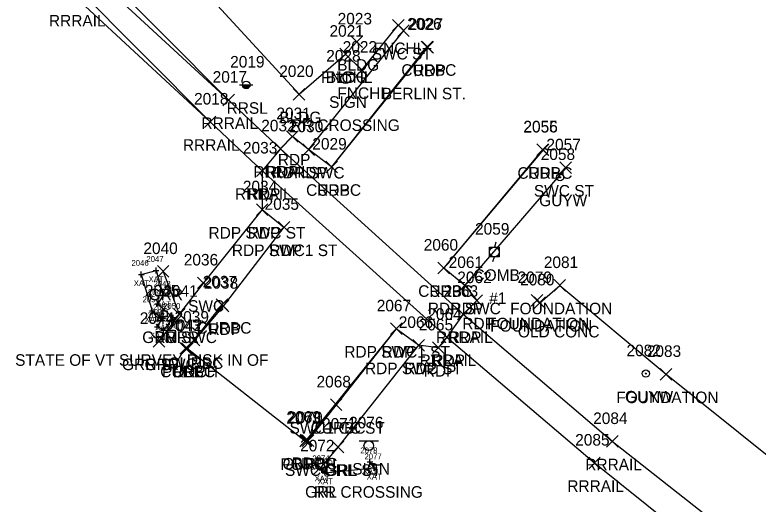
# Model space of a CAD drawing. Extents: x 1635588 to 1637550, y 621583 to 623638.
# Drawn here: x 1637037.4 to 1637166, y 621810.1 to 621894.7 of the extents above; entities that cross this region are included whole.
import ezdxf

# ---------------------------------------------------------------- set-up
doc = ezdxf.new("R2010")
doc.units = 0
for name, color, linetype in [('B_A', 7, 'Continuous'), ('B_I', 7, 'Continuous'), ('B_TIC', 7, 'Continuous'), ('BSUBM', 7, 'Continuous'), ('C_A', 7, 'Continuous'), ('C_C', 7, 'Continuous'), ('C_I', 7, 'Continuous'), ('CPBM', 7, 'Continuous'), ('L_A', 7, 'Continuous'), ('L_C', 7, 'Continuous'), ('L_I', 7, 'Continuous'), ('L_TIC', 7, 'Continuous'), ('LBC', 7, 'Continuous'), ('LBF', 7, 'Continuous'), ('LFNC', 7, 'Continuous'), ('P_A', 7, 'Continuous'), ('P_C', 7, 'Continuous'), ('P_I', 7, 'Continuous'), ('P_TIC', 7, 'Continuous'), ('PET', 7, 'Continuous'), ('R_A', 7, 'Continuous'), ('R_I', 7, 'Continuous'), ('R_TIC', 7, 'Continuous'), ('RC', 7, 'Continuous'), ('RGR', 7, 'Continuous'), ('RR', 7, 'Continuous'), ('RR_T', 7, 'Continuous'), ('RSW', 7, 'Continuous'), ('S_A', 7, 'Continuous'), ('S_C', 7, 'Continuous'), ('S_I', 7, 'Continuous'), ('SSGN', 7, 'Continuous'), ('U_A', 7, 'Continuous'), ('U_C', 7, 'Continuous'), ('U_I', 7, 'Continuous'), ('UP', 7, 'Continuous'), ('UPGW', 7, 'Continuous')]:
    doc.layers.add(name, color=color, linetype=linetype)

msp = doc.modelspace()

# ---------------------------------------------------------------- linework, layer by layer
at = {"layer": 'B_TIC'}
for p, q in [((1637059.28, 621849.83), (1637059.36, 621849.83)), ((1637059.28, 621849.83), (1637059.36, 621849.83)), ((1637061.83, 621850.52), (1637061.91, 621850.52)), ((1637063.07, 621846.22), (1637063.14, 621846.22)), ((1637062.11, 621844.77), (1637062.18, 621844.77)), ((1637061.17, 621843.54), (1637061.25, 621843.54)), ((1637061.17, 621843.54), (1637061.25, 621843.54)), ((1637062.98, 621842.2), (1637063.05, 621842.2)), ((1637064.77, 621842.38), (1637064.85, 621842.38)), ((1637062.05, 621840.8), (1637062.12, 621840.8)), ((1637063.12, 621840.2), (1637063.2, 621840.2)), ((1637098.86, 621817.41), (1637098.93, 621817.41)), ((1637099.59, 621816.37), (1637099.66, 621816.37)), ((1637090.56, 621816.04), (1637090.63, 621816.04)), ((1637091.11, 621815.55), (1637091.19, 621815.55))]:
    msp.add_line(p, q, dxfattribs=at)
for points in [[(1637058.78, 621849.83), (1637059.78, 621849.83)], [(1637058.78, 621849.83), (1637059.78, 621849.83)], [(1637059.28, 621849.33), (1637059.28, 621850.33)], [(1637059.28, 621849.33), (1637059.28, 621850.33)], [(1637061.33, 621850.52), (1637062.33, 621850.52)], [(1637061.83, 621850.02), (1637061.83, 621851.02)], [(1637062.56, 621846.22), (1637063.56, 621846.22)], [(1637063.06, 621845.72), (1637063.06, 621846.72)], [(1637061.6, 621844.77), (1637062.6, 621844.77)], [(1637062.1, 621844.27), (1637062.1, 621845.27)], [(1637060.67, 621843.54), (1637061.67, 621843.54)], [(1637060.67, 621843.54), (1637061.67, 621843.54)], [(1637061.17, 621843.04), (1637061.17, 621844.04)], [(1637061.17, 621843.04), (1637061.17, 621844.04)], [(1637062.47, 621842.2), (1637063.47, 621842.2)], [(1637062.97, 621841.7), (1637062.97, 621842.7)], [(1637064.27, 621842.38), (1637065.27, 621842.38)], [(1637064.77, 621841.88), (1637064.77, 621842.88)], [(1637061.54, 621840.8), (1637062.54, 621840.8)], [(1637062.04, 621840.3), (1637062.04, 621841.3)], [(1637062.62, 621840.2), (1637063.62, 621840.2)], [(1637063.12, 621839.7), (1637063.12, 621840.7)], [(1637098.86, 621816.91), (1637098.86, 621817.91)], [(1637090.55, 621815.54), (1637090.55, 621816.54)], [(1637098.36, 621817.41), (1637099.36, 621817.41)], [(1637099.08, 621816.37), (1637100.08, 621816.37)], [(1637099.58, 621815.87), (1637099.58, 621816.87)], [(1637090.05, 621816.04), (1637091.05, 621816.04)], [(1637090.61, 621815.55), (1637091.61, 621815.55)], [(1637091.11, 621815.05), (1637091.11, 621816.05)]]:
    msp.add_lwpolyline(points, dxfattribs=at)
at = {"layer": 'BSUBM'}
for points in [[(1637059.28, 621849.83), (1637061.83, 621850.52), (1637063.06, 621846.22), (1637062.1, 621844.77), (1637064.77, 621842.38), (1637063.12, 621840.2), (1637062.04, 621840.8), (1637062.97, 621842.2), (1637061.17, 621843.54)], [(1637059.28, 621849.83), (1637061.17, 621843.54)], [(1637090.55, 621816.04), (1637091.11, 621815.55), (1637099.58, 621816.37), (1637098.86, 621817.41)]]:
    msp.add_lwpolyline(points, dxfattribs=at)
at = {"layer": 'CPBM'}
for p, q in [((1637062.74, 621842.53), (1637062.74, 621843.53)), ((1637062.74, 621843.53), (1637063.74, 621843.53)), ((1637063.74, 621843.53), (1637063.74, 621842.53)), ((1637063.74, 621842.53), (1637062.74, 621842.53)), ((1637063.24, 621843.04), (1637063.24, 621843.04)), ((1637063.24, 621843.04), (1637063.24, 621843.04))]:
    msp.add_line(p, q, dxfattribs=at)
at = {"layer": 'L_TIC'}
for points in [[(1637102.75, 621891.96), (1637104.75, 621893.96)], [(1637104.75, 621891.96), (1637102.75, 621893.96)], [(1637095.59, 621889.08), (1637097.59, 621891.08)], [(1637097.59, 621889.08), (1637095.59, 621891.08)], [(1637093.62, 621886.96), (1637095.62, 621888.96)], [(1637095.62, 621886.96), (1637093.62, 621888.96)], [(1637093.62, 621886.96), (1637095.62, 621888.96)], [(1637095.62, 621886.96), (1637093.62, 621888.96)], [(1637096.47, 621884.2), (1637098.47, 621886.2)], [(1637098.47, 621884.2), (1637096.47, 621886.2)], [(1637085.58, 621880), (1637087.58, 621882)], [(1637087.58, 621880), (1637085.58, 621882)], [(1637130.72, 621846.95), (1637132.72, 621848.95)], [(1637132.72, 621846.95), (1637130.72, 621848.95)], [(1637126.75, 621844.35), (1637128.75, 621846.35)], [(1637128.75, 621844.35), (1637126.75, 621846.35)], [(1637127.26, 621843.95), (1637129.26, 621845.95)], [(1637129.26, 621843.95), (1637127.26, 621845.95)], [(1637066.26, 621836.04), (1637068.26, 621838.04)], [(1637068.26, 621836.04), (1637066.26, 621838.04)], [(1637149.11, 621831.58), (1637151.11, 621833.58)], [(1637151.11, 621831.58), (1637149.11, 621833.58)], [(1637086.72, 621820.02), (1637088.72, 621822.02)], [(1637088.72, 621820.02), (1637086.72, 621822.02)]]:
    msp.add_lwpolyline(points, dxfattribs=at)
at = {"layer": 'LBC'}
for points in [[(1636885.66, 622098.09), (1636886.49, 622098.53), (1637000.47, 621974.51), (1637086.58, 621881), (1637094.62, 621887.96), (1637096.59, 621890.08)], [(1637127.75, 621845.35), (1637128.26, 621844.95), (1637131.72, 621847.95), (1637150.11, 621832.58), (1637193.82, 621797.61), (1637199.24, 621804.01)]]:
    msp.add_lwpolyline(points, dxfattribs=at)
at = {"layer": 'LBF'}
msp.add_lwpolyline([(1637067.26, 621837.04), (1637087.72, 621821.02)], dxfattribs=at)
at = {"layer": 'LFNC'}
msp.add_lwpolyline([(1637094.62, 621887.96), (1637097.47, 621885.2), (1637103.75, 621892.96)], dxfattribs=at)
at = {"layer": 'P_TIC'}
for points in [[(1637107.88, 621888.13), (1637109.88, 621890.13)], [(1637109.88, 621888.13), (1637107.88, 621890.13)], [(1637084.43, 621872.7), (1637086.43, 621874.7)], [(1637086.43, 621872.7), (1637084.43, 621874.7)], [(1637082.38, 621870.59), (1637084.38, 621872.59)], [(1637084.38, 621870.59), (1637082.38, 621872.59)], [(1637087.24, 621870.44), (1637089.24, 621872.44)], [(1637089.24, 621870.44), (1637087.24, 621872.44)], [(1637127.74, 621870.42), (1637129.74, 621872.42)], [(1637129.74, 621870.42), (1637127.74, 621872.42)], [(1637091.22, 621867.44), (1637093.22, 621869.44)], [(1637093.22, 621867.44), (1637091.22, 621869.44)], [(1637079.21, 621866.76), (1637081.21, 621868.76)], [(1637081.21, 621866.76), (1637079.21, 621868.76)], [(1637079.2, 621860.05), (1637081.2, 621862.05)], [(1637081.2, 621860.05), (1637079.2, 621862.05)], [(1637082.96, 621857.02), (1637084.96, 621859.02)], [(1637084.96, 621857.02), (1637082.96, 621859.02)], [(1637110.63, 621849.97), (1637112.63, 621851.97)], [(1637112.63, 621849.97), (1637110.63, 621851.97)], [(1637114.3, 621846.96), (1637116.3, 621848.96)], [(1637116.3, 621846.96), (1637114.3, 621848.96)], [(1637116.35, 621844.34), (1637118.35, 621846.34)], [(1637118.35, 621844.34), (1637116.35, 621846.34)], [(1637072.43, 621843.38), (1637074.43, 621845.38)], [(1637074.43, 621843.38), (1637072.43, 621845.38)], [(1637114.01, 621841.98), (1637116.01, 621843.98)], [(1637116.01, 621841.98), (1637114.01, 621843.98)], [(1637102.41, 621839.46), (1637104.41, 621841.46)], [(1637104.41, 621839.46), (1637102.41, 621841.46)], [(1637111.17, 621838), (1637113.17, 621840)], [(1637113.17, 621838), (1637111.17, 621840)], [(1637106.28, 621836.59), (1637108.28, 621838.59)], [(1637108.28, 621836.59), (1637106.28, 621838.59)], [(1637109.69, 621836.17), (1637111.69, 621838.17)], [(1637111.69, 621836.17), (1637109.69, 621838.17)], [(1637066.26, 621836.04), (1637068.26, 621838.04)], [(1637068.26, 621836.04), (1637066.26, 621838.04)], [(1637086.82, 621820.19), (1637088.82, 621822.19)], [(1637088.82, 621820.19), (1637086.82, 621822.19)]]:
    msp.add_lwpolyline(points, dxfattribs=at)
at = {"layer": 'PET'}
for points in [[(1637108.88, 621889.13), (1637092.22, 621868.44), (1637088.24, 621871.44), (1637085.43, 621873.7), (1637083.38, 621871.59), (1637080.21, 621867.76), (1637080.2, 621861.05), (1637083.96, 621858.02), (1637073.43, 621844.38), (1637067.26, 621837.04)], [(1637128.74, 621871.42), (1637111.63, 621850.97), (1637115.3, 621847.96), (1637117.35, 621845.34), (1637115.01, 621842.98), (1637112.17, 621839), (1637110.69, 621837.17), (1637107.28, 621837.59), (1637103.41, 621840.46), (1637087.82, 621821.19)]]:
    msp.add_lwpolyline(points, dxfattribs=at)
at = {"layer": 'R_TIC'}
for points in [[(1637103.67, 621891.02), (1637105.67, 621893.02)], [(1637105.67, 621891.02), (1637103.67, 621893.02)], [(1637107.71, 621888.2), (1637109.71, 621890.2)], [(1637109.71, 621888.2), (1637107.71, 621890.2)], [(1637073.4, 621879.01), (1637075.4, 621881.01)], [(1637075.4, 621879.01), (1637073.4, 621881.01)], [(1637073.4, 621879.01), (1637075.4, 621881.01)], [(1637075.4, 621879.01), (1637073.4, 621881.01)], [(1637070.19, 621875.23), (1637072.19, 621877.23)], [(1637072.19, 621875.23), (1637070.19, 621877.23)], [(1637070.19, 621875.23), (1637072.19, 621877.23)], [(1637072.19, 621875.23), (1637070.19, 621877.23)], [(1637082.38, 621870.59), (1637084.38, 621872.59)], [(1637084.38, 621870.59), (1637082.38, 621872.59)], [(1637087.24, 621870.44), (1637089.24, 621872.44)], [(1637089.24, 621870.44), (1637087.24, 621872.44)], [(1637127.81, 621870.39), (1637129.81, 621872.39)], [(1637129.81, 621870.39), (1637127.81, 621872.39)], [(1637091.22, 621867.44), (1637093.22, 621869.44)], [(1637093.22, 621867.44), (1637091.22, 621869.44)], [(1637131.74, 621867.31), (1637133.74, 621869.31)], [(1637133.74, 621867.31), (1637131.74, 621869.31)], [(1637079.21, 621866.76), (1637081.21, 621868.76)], [(1637081.21, 621866.76), (1637079.21, 621868.76)], [(1637079.2, 621860.05), (1637081.2, 621862.05)], [(1637081.2, 621860.05), (1637079.2, 621862.05)], [(1637082.96, 621857.02), (1637084.96, 621859.02)], [(1637084.96, 621857.02), (1637082.96, 621859.02)], [(1637062.06, 621849.37), (1637064.06, 621851.37)], [(1637064.06, 621849.37), (1637062.06, 621851.37)], [(1637110.63, 621849.97), (1637112.63, 621851.97)], [(1637112.63, 621849.97), (1637110.63, 621851.97)], [(1637069.02, 621847.39), (1637071.02, 621849.39)], [(1637071.02, 621847.39), (1637069.02, 621849.39)], [(1637114.3, 621846.96), (1637116.3, 621848.96)], [(1637116.3, 621846.96), (1637114.3, 621848.96)], [(1637072.24, 621843.6), (1637074.24, 621845.6)], [(1637074.24, 621843.6), (1637072.24, 621845.6)], [(1637064.86, 621841.98), (1637066.86, 621843.98)], [(1637066.86, 621841.98), (1637064.86, 621843.98)], [(1637064.86, 621841.98), (1637066.86, 621843.98)], [(1637066.86, 621841.98), (1637064.86, 621843.98)], [(1637114.01, 621841.98), (1637116.01, 621843.98)], [(1637116.01, 621841.98), (1637114.01, 621843.98)], [(1637102.41, 621839.46), (1637104.41, 621841.46)], [(1637104.41, 621839.46), (1637102.41, 621841.46)], [(1637067.39, 621837.5), (1637069.39, 621839.5)], [(1637069.39, 621837.5), (1637067.39, 621839.5)], [(1637111.17, 621838), (1637113.17, 621840)], [(1637113.17, 621838), (1637111.17, 621840)], [(1637061.36, 621837.29), (1637063.36, 621839.29)], [(1637063.36, 621837.29), (1637061.36, 621839.29)], [(1637061.36, 621837.29), (1637063.36, 621839.29)], [(1637063.36, 621837.29), (1637061.36, 621839.29)], [(1637106.28, 621836.59), (1637108.28, 621838.59)], [(1637108.28, 621836.59), (1637106.28, 621838.59)], [(1637065.97, 621836.06), (1637067.97, 621838.06)], [(1637067.97, 621836.06), (1637065.97, 621838.06)], [(1637092, 621826.3), (1637094, 621828.3)], [(1637094, 621826.3), (1637092, 621828.3)], [(1637092, 621826.3), (1637094, 621828.3)], [(1637094, 621826.3), (1637092, 621828.3)], [(1637087.13, 621820.1), (1637089.13, 621822.1)], [(1637089.13, 621820.1), (1637087.13, 621822.1)], [(1637139.82, 621819.97), (1637141.82, 621821.97)], [(1637141.82, 621819.97), (1637139.82, 621821.97)], [(1637092.34, 621819), (1637094.34, 621821)], [(1637094.34, 621819), (1637092.34, 621821)], [(1637092.34, 621819), (1637094.34, 621821)], [(1637094.34, 621819), (1637092.34, 621821)], [(1637136.72, 621816.24), (1637138.72, 621818.24)], [(1637138.72, 621816.24), (1637136.72, 621818.24)], [(1637089.1, 621815.24), (1637091.1, 621817.24)], [(1637091.1, 621815.24), (1637089.1, 621817.24)]]:
    msp.add_lwpolyline(points, dxfattribs=at)
at = {"layer": 'RC'}
for points in [[(1637108.71, 621889.2), (1637092.22, 621868.44)], [(1637128.81, 621871.39), (1637111.63, 621850.97)], [(1637073.24, 621844.6), (1637068.39, 621838.5), (1637066.97, 621837.06)], [(1637093, 621827.3), (1637088.13, 621821.1)]]:
    msp.add_lwpolyline(points, dxfattribs=at)
at = {"layer": 'RGR'}
for points in [[(1637063.06, 621850.37), (1637065.86, 621842.98), (1637062.36, 621838.29)], [(1637093.34, 621820), (1637090.1, 621816.24)]]:
    msp.add_lwpolyline(points, dxfattribs=at)
at = {"layer": 'RR'}
for points in [[(1636647.57, 622303.46), (1636681.53, 622274.07), (1636698.35, 622258.6), (1636736.07, 622216.66), (1636772.81, 622171.31), (1636793.48, 622145.5), (1636799.12, 622138.4), (1636815.41, 622118.42), (1636845.94, 622085.12), (1636908.55, 622026.21), (1636983.07, 621959.74), (1637027.08, 621922.66), (1637050.39, 621902.14), (1637074.4, 621880.01)], [(1636645.23, 622298.69), (1636678.25, 622270.68), (1636695.49, 622253.83), (1636732.46, 622213.3), (1636769.51, 622167.71), (1636788.83, 622143.09), (1636795.06, 622135.55), (1636811.52, 622115.54), (1636841.96, 622081.95), (1636905.16, 622022.78), (1636979.87, 621956.02), (1637024.02, 621918.73), (1637048, 621897.73), (1637071.19, 621876.23)], [(1637026.25, 621930.62), (1637051.37, 621903.17), (1637074.4, 621880.01), (1637083.38, 621871.59), (1637115.01, 621842.98), (1637140.82, 621820.97), (1637163.57, 621803.06), (1637178.63, 621791.62), (1637197.58, 621777.98), (1637205.69, 621772.14), (1637224.52, 621759.19), (1637253.9, 621739.72), (1637289.58, 621717.58), (1637320.59, 621699.03)], [(1637027.08, 621922.66), (1637047.82, 621899.75), (1637071.19, 621876.23), (1637080.21, 621867.76), (1637112.17, 621839), (1637137.72, 621817.24), (1637160.21, 621799.22), (1637175.91, 621787.14), (1637194.67, 621774), (1637203.09, 621767.92), (1637221.71, 621755.12), (1637251.64, 621735.37), (1637287.01, 621713.34), (1637318.07, 621694.59)]]:
    msp.add_lwpolyline(points, dxfattribs=at)
at = {"layer": 'RR_T'}
for p, q in [((1637076.3, 621882.63), (1637078.59, 621882.63)), ((1637076.79, 621882.55), (1637078.09, 621882.55)), ((1637076.81, 621882.46), (1637078.08, 621882.46)), ((1637076.84, 621882.38), (1637078.05, 621882.38)), ((1637076.88, 621882.3), (1637078.01, 621882.3)), ((1637076.93, 621882.22), (1637077.96, 621882.22)), ((1637077.01, 621882.14), (1637077.88, 621882.14)), ((1637077.13, 621882.05), (1637077.76, 621882.05)), ((1637077.44, 621882.55), (1637077.44, 621882.71))]:
    msp.add_line(p, q, dxfattribs=at)
msp.add_circle((1637077.44, 621882.63), 0.656, dxfattribs=at)
at = {"layer": 'RSW'}
for points in [[(1637104.67, 621892.02), (1637088.24, 621871.44)], [(1637132.74, 621868.31), (1637115.3, 621847.96)], [(1637080.2, 621861.05), (1637070.02, 621848.39), (1637065.86, 621842.98), (1637062.36, 621838.29)], [(1637103.41, 621840.46), (1637093, 621827.3)], [(1637107.28, 621837.59), (1637093.34, 621820)]]:
    msp.add_lwpolyline(points, dxfattribs=at)
at = {"layer": 'SSGN'}
for p, q in [((1637093, 621884.51), (1637096.34, 621884.51)), ((1637094.65, 621883.68), (1637094.65, 621883.68)), ((1637097.01, 621821.08), (1637100.34, 621821.08)), ((1637098.65, 621820.24), (1637098.65, 621820.24))]:
    msp.add_line(p, q, dxfattribs=at)
for centre in [(1637094.65, 621883.68), (1637098.65, 621820.24)]:
    msp.add_circle(centre, 0.833, dxfattribs=at)
at = {"layer": 'UP'}
for p, q in [((1637120.64, 621855.4), (1637120.39, 621854.57)), ((1637119.55, 621852.9), (1637119.55, 621854.57)), ((1637119.55, 621854.57), (1637121.22, 621854.57)), ((1637120.39, 621853.73), (1637120.39, 621853.73)), ((1637121.22, 621854.57), (1637121.22, 621852.9)), ((1637121.22, 621852.9), (1637119.55, 621852.9)), ((1637120.14, 621852.07), (1637120.39, 621852.9))]:
    msp.add_line(p, q, dxfattribs=at)
msp.add_circle((1637120.39, 621853.73), 0.833, dxfattribs=at)
at = {"layer": 'UPGW'}
for centre, radius in [((1637131.75, 621866.64), 0.625), ((1637131.75, 621866.64), 0.0833), ((1637146.6, 621832.7), 0.625), ((1637146.6, 621832.7), 0.0833)]:
    msp.add_circle(centre, radius, dxfattribs=at)

# ---------------------------------------------------------------- texts
at = {"layer": 'B_A'}
for p in [(1637057.98, 621847.83), (1637057.98, 621847.83), (1637060.53, 621848.52), (1637061.77, 621844.22), (1637060.81, 621842.77), (1637059.87, 621841.54), (1637059.87, 621841.54), (1637061.68, 621840.2), (1637063.48, 621840.38), (1637060.75, 621838.8), (1637061.82, 621838.2), (1637097.56, 621815.41), (1637089.26, 621814.04), (1637098.29, 621814.37), (1637089.82, 621813.55)]:
    msp.add_text('XAT', height=1, dxfattribs=at).set_placement(p)
at = {"layer": 'B_I'}
for s, p in [('2046', (1637057.58, 621851.33)), ('2046', (1637057.58, 621851.33)), ('2047', (1637060.16, 621852.02)), ('2048', (1637061.39, 621847.72)), ('2049', (1637060.43, 621846.27)), ('2054', (1637059.5, 621845.04)), ('2054', (1637059.5, 621845.04)), ('2053', (1637061.3, 621843.7)), ('2050', (1637063.06, 621843.88)), ('2052', (1637060.37, 621842.3)), ('2051', (1637061.73, 621841.7)), ('2078', (1637097.19, 621818.91)), ('2077', (1637097.91, 621817.87)), ('2074', (1637088.89, 621817.54)), ('2075', (1637089.44, 621817.05))]:
    msp.add_text(s, height=1, dxfattribs=at).set_placement(p)
at = {"layer": 'C_A'}
msp.add_text('BM', height=2, dxfattribs=at).set_placement((1637061.56, 621838.04))
at = {"layer": 'C_C'}
msp.add_text('STATE OF VT SURVEY DISK IN OF', height=2, dxfattribs=at).set_placement((1637037.44, 621834.04))
at = {"layer": 'C_I'}
msp.add_text('2045', height=2, dxfattribs=at).set_placement((1637059.9, 621846.04))
at = {"layer": 'L_A'}
for s, p in [('FNCHL', (1637099.5, 621887.96)), ('BLDG', (1637093.18, 621885.08)), ('FNCHL', (1637090.37, 621882.96)), ('BLDG', (1637091.21, 621882.96)), ('FNCHL', (1637093.22, 621880.2)), ('BLDG', (1637083.17, 621876)), ('FOUNDATION', (1637123.12, 621842.95)), ('FOUNDATION', (1637119.14, 621840.35)), ('FOUNDATION', (1637119.66, 621839.95)), ('PORCH', (1637062.88, 621832.04)), ('FOUNDATION', (1637141.5, 621827.58)), ('PORCH', (1637083.34, 621816.02))]:
    msp.add_text(s, height=2, dxfattribs=at).set_placement(p)
at = {"layer": 'L_C'}
msp.add_text('OLD CONC', height=2, dxfattribs=at).set_placement((1637124.47, 621838.95))
at = {"layer": 'L_I'}
for s, p in [('2023', (1637093.26, 621893.08)), ('2021', (1637091.85, 621890.96)), ('2021', (1637091.85, 621890.96)), ('2022', (1637094.13, 621888.2)), ('2020', (1637083.15, 621884)), ('2081', (1637128.95, 621850.95)), ('2079', (1637124.4, 621848.35)), ('2080', (1637124.84, 621847.95)), ('2042', (1637063.92, 621840.04)), ('2083', (1637146.77, 621835.58)), ('2073', (1637084.38, 621824.02))]:
    msp.add_text(s, height=2, dxfattribs=at).set_placement(p)
at = {"layer": 'P_A'}
for p in [(1637106.37, 621884.13), (1637082.91, 621868.7), (1637080.87, 621866.59), (1637085.73, 621866.44), (1637126.23, 621866.42), (1637089.71, 621863.44), (1637077.7, 621862.76), (1637077.69, 621856.05), (1637081.45, 621853.02), (1637109.12, 621845.97), (1637112.79, 621842.96), (1637114.84, 621840.34), (1637070.92, 621839.38), (1637112.5, 621837.98), (1637100.9, 621835.46), (1637109.66, 621834), (1637104.77, 621832.59), (1637064.74, 621832.04), (1637108.17, 621832.17), (1637085.3, 621816.19)]:
    msp.add_text('RDP', height=2, dxfattribs=at).set_placement(p)
at = {"layer": 'P_C'}
msp.add_text('BERLIN ST.', height=2, dxfattribs=at).set_placement((1637100.9, 621880.13))
at = {"layer": 'P_I'}
for s, p in [('2027', (1637105.55, 621892.13)), ('2031', (1637082.66, 621876.7)), ('2032', (1637080.04, 621874.59)), ('2030', (1637084.82, 621874.44)), ('2055', (1637125.41, 621874.42)), ('2029', (1637088.88, 621871.44)), ('2033', (1637076.87, 621870.76)), ('2034', (1637076.86, 621864.05)), ('2035', (1637080.62, 621861.02)), ('2060', (1637108.16, 621853.97)), ('2061', (1637112.48, 621850.96)), ('2062', (1637113.97, 621848.34)), ('2038', (1637070.09, 621847.38)), ('2063', (1637111.62, 621845.98)), ('2067', (1637100.03, 621843.46)), ('2064', (1637108.78, 621842)), ('2042', (1637063.92, 621840.04)), ('2066', (1637103.84, 621840.59)), ('2065', (1637107.3, 621840.17)), ('2069', (1637084.42, 621824.19))]:
    msp.add_text(s, height=2, dxfattribs=at).set_placement(p)
at = {"layer": 'R_A'}
for s, p in [('RRRAIL', (1637043.29, 621892.73)), ('SWC ST', (1637099.16, 621887.02)), ('CURBC', (1637104.29, 621884.2)), ('RRSL', (1637074.04, 621877.63)), ('RRRAIL', (1637069.69, 621875.01)), ('RRRAIL', (1637069.69, 621875.01)), ('RRRAIL', (1637066.48, 621871.23)), ('RRRAIL', (1637066.48, 621871.23)), ('RRRAIL', (1637078.67, 621866.59)), ('RDP SWC', (1637081.83, 621866.44)), ('CURBC', (1637124.39, 621866.39)), ('CURBC', (1637087.81, 621863.44)), ('SWC ST', (1637127.23, 621863.31)), ('RRRAIL', (1637075.5, 621862.76)), ('RDP SWC ST', (1637070.91, 621856.05)), ('RDP SWC1 ST', (1637074.96, 621853.02)), ('GRR', (1637060.55, 621845.37)), ('CURBC', (1637107.21, 621845.97)), ('SWC', (1637067.38, 621843.39)), ('RDP SWC', (1637108.88, 621842.96)), ('CURBC', (1637068.83, 621839.6)), ('GRR SWC', (1637059.44, 621837.98)), ('GRR', (1637063.35, 621837.98)), ('RRRAIL', (1637110.3, 621837.98)), ('RDP SWC1 ST', (1637094.41, 621835.46)), ('RRRAIL', (1637107.46, 621834)), ('GRR SWC', (1637055.94, 621833.29)), ('GRR', (1637059.85, 621833.29)), ('CURBC', (1637063.97, 621833.5)), ('RDP SWC ST', (1637097.99, 621832.59)), ('CURBC', (1637062.55, 621832.06)), ('SWC1 CC ST', (1637084.94, 621822.3)), ('CURBC', (1637088.58, 621822.3)), ('CURBC', (1637083.72, 621816.1)), ('RRRAIL', (1637136.12, 621815.97)), ('SWC GRL ST', (1637084.15, 621815)), ('GRL', (1637090.88, 621815)), ('RRRAIL', (1637133.01, 621812.24)), ('GRL', (1637087.64, 621811.24))]:
    msp.add_text(s, height=2, dxfattribs=at).set_placement(p)
at = {"layer": 'R_I'}
for s, p in [('2026', (1637105.31, 621892.2)), ('2019', (1637074.66, 621885.63)), ('2017', (1637071.63, 621883.01)), ('2017', (1637071.63, 621883.01)), ('2018', (1637068.41, 621879.23)), ('2018', (1637068.41, 621879.23)), ('2032', (1637080.04, 621874.59)), ('2030', (1637084.82, 621874.44)), ('2056', (1637125.42, 621874.39)), ('2029', (1637088.88, 621871.44)), ('2057', (1637129.4, 621871.31)), ('2033', (1637076.87, 621870.76)), ('2034', (1637076.86, 621864.05)), ('2035', (1637080.62, 621861.02)), ('2040', (1637059.64, 621853.37)), ('2060', (1637108.16, 621853.97)), ('2036', (1637066.63, 621851.39)), ('2061', (1637112.48, 621850.96)), ('2037', (1637069.91, 621847.6)), ('2041', (1637063.09, 621845.98)), ('2041', (1637063.09, 621845.98)), ('2063', (1637111.62, 621845.98)), ('2067', (1637100.03, 621843.46)), ('2044', (1637059.02, 621841.29)), ('2044', (1637059.02, 621841.29)), ('2039', (1637065.04, 621841.5)), ('2064', (1637108.78, 621842)), ('2043', (1637063.63, 621840.06)), ('2066', (1637103.84, 621840.59)), ('2068', (1637089.61, 621830.3)), ('2068', (1637089.61, 621830.3)), ('2070', (1637084.71, 621824.1)), ('2084', (1637137.49, 621823.97)), ('2071', (1637090.56, 621823)), ('2071', (1637090.56, 621823)), ('2085', (1637134.38, 621820.24)), ('2072', (1637086.76, 621819.24))]:
    msp.add_text(s, height=2, dxfattribs=at).set_placement(p)
at = {"layer": 'S_A'}
for p in [(1637091.79, 621878.66), (1637095.79, 621815.22)]:
    msp.add_text('SIGN', height=2, dxfattribs=at).set_placement(p)
at = {"layer": 'S_C'}
for p in [(1637085.14, 621874.66), (1637089.14, 621811.22)]:
    msp.add_text('RR CROSSING', height=2, dxfattribs=at).set_placement(p)
at = {"layer": 'S_I'}
for s, p in [('2028', (1637091.29, 621886.66)), ('2076', (1637095.24, 621823.22))]:
    msp.add_text(s, height=2, dxfattribs=at).set_placement(p)
at = {"layer": 'U_A'}
for s, p in [('GUYW', (1637128.15, 621861.64)), ('COMB', (1637116.77, 621848.73)), ('GUYW', (1637143, 621827.7))]:
    msp.add_text(s, height=2, dxfattribs=at).set_placement(p)
at = {"layer": 'U_C'}
msp.add_text('#1', height=2, dxfattribs=at).set_placement((1637119.49, 621844.73))
at = {"layer": 'U_I'}
for s, p in [('2058', (1637128.41, 621869.64)), ('2059', (1637117.04, 621856.73)), ('2082', (1637143.26, 621835.7))]:
    msp.add_text(s, height=2, dxfattribs=at).set_placement(p)

doc.saveas('drawing.dxf')
